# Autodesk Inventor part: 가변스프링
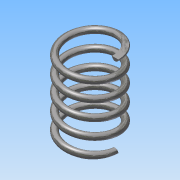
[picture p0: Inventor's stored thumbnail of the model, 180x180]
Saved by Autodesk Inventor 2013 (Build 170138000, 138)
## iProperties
Created: 2018-10
Part Number: 가변스프링
Material: 스테인리스강
Document SubType Name: Modeling
Designer: Administrator
Density: 8.08 g/cm^3
Mass: 6.28308 g
Surface Area: 15.7652 cm^2
Volume: 0.777609 cm^3
Author: Administrator
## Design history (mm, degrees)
sketch "스케치1"
  geometry: L1 (0, 0)-(0, 25.77); L2 (0, 0)-(8, 0); L3 (0, 25.77)-(8, 25.77); C1 r 1 at (8, 0)
  constraints: 6 end point, 1 centre point, 1 coincident, 1 parallel, 1 perpendicular, 1 vertical
  dimensions: "d0" = 25.76996 distance of L1.start L1.end (derived); "d1" = 8 distance of L1.start L2.end; "d2" = 2 diameter of C1; "d3" = 8 distance of L1.end L3.end
feature "코일1" pitch "d4" = 10; turns "d6" = 5; dims "d5" = 25.76996 (= d0), "d7" = 0, angle "d8" = 90 deg, angle "d9" = 90 deg, "d10" = 0, "d11" = 0
sketch "스케치2"
  geometry: L1 (25.77, 11)-(0, 11); L2 (0, 11)-(0, -11); L3 (0, -11)-(25.77, -11); L4 (25.77, -11)-(25.77, 11); 2 further points
  constraints: 8 end point, 2 parallel, 1 coincident, 1 horizontal, 1 midpoint, 1 perpendicular
  dimensions: "d12" = 25.76996 distance of L1.start L1.end (derived); "d14" = 22 distance of L3.end L1.start
extrude "돌출1" sketch "스케치2" stored distance "d15" = 0; taper "d16" = 0 deg
node "솔리드1"
